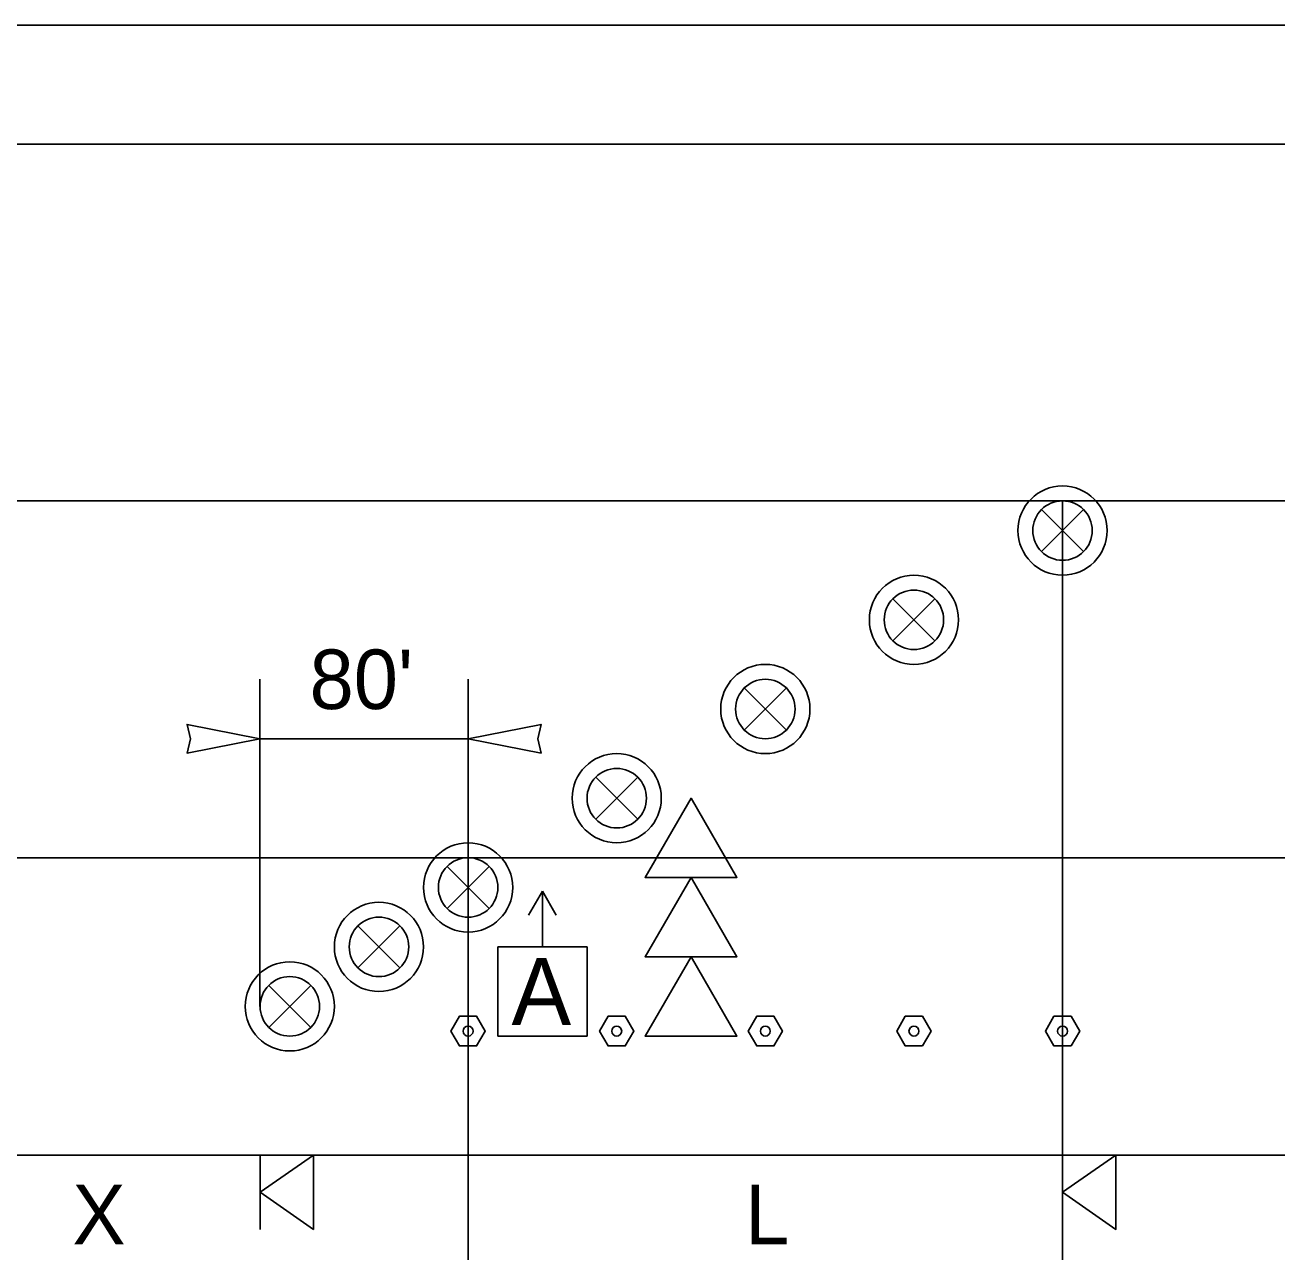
# Model space of a CAD drawing. Extents: x 99958 to 100136, y 99935 to 100013.
# Drawn here: x 100025.894 to 100027.579, y 99975.105 to 99976.756 of the extents above; entities that cross this region are included whole.
import ezdxf

# ---------------------------------------------------------------- set-up
doc = ezdxf.new("R2010")
doc.units = 0
for name, color, linetype in [('RD_ED_ShoulderPavedEdge', 7, 'Continuous'), ('RD_MK_LineEdgeWhite', 7, 'Continuous'), ('RD_MK_LineEdgeYellow', 7, 'Continuous'), ('RD_MK_LineLane', 7, 'Continuous'), ('TR_WZ_PortableSignMountBlk-Wht', 7, 'Continuous'), ('TR_WZ_SequentialArrowSign', 7, 'Continuous'), ('TR_WZ_TrafficSafetyDrum', 7, 'Continuous'), ('TR_WZ_TubularMarker', 7, 'Continuous'), ('TR_WZ_WorkZoneDetails', 7, 'Continuous'), ('TR_WZ_WorkZoneTextCurrent', 7, 'Continuous')]:
    doc.layers.add(name, color=color, linetype=linetype)

msp = doc.modelspace()

# ---------------------------------------------------------------- linework, layer by layer
at = {"layer": 'RD_ED_ShoulderPavedEdge'}
for p, q in [((100021.7753, 99976.7557), (100035.62, 99976.7557)), ((100021.7753, 99975.2357), (100035.62, 99975.2357))]:
    msp.add_line(p, q, dxfattribs=at)
at = {"layer": 'RD_MK_LineEdgeWhite'}
msp.add_line((100021.7753, 99975.6357), (100035.62, 99975.6357), dxfattribs=at)
at = {"layer": 'RD_MK_LineEdgeYellow'}
msp.add_line((100021.7753, 99976.5957), (100035.62, 99976.5957), dxfattribs=at)
at = {"layer": 'RD_MK_LineLane'}
msp.add_lwpolyline([(100035.62, 99976.1157), (100021.7753, 99976.1157)], dxfattribs=at)
at = {"layer": 'TR_WZ_PortableSignMountBlk-Wht'}
for p, q in [((100026.2103, 99975.1357), (100026.2103, 99975.2357)), ((100027.2902, 99975.1357), (100027.2902, 99975.2357))]:
    msp.add_line(p, q, dxfattribs=at)
for points in [[(100026.2103, 99975.1856), (100026.2821, 99975.2357), (100026.2821, 99975.1357)], [(100027.2902, 99975.1856), (100027.3621, 99975.2357), (100027.3621, 99975.1357)]]:
    msp.add_lwpolyline(points, close=True, dxfattribs=at)
at = {"layer": 'TR_WZ_SequentialArrowSign'}
for points in [[(100026.7903, 99975.7157), (100026.7285, 99975.6091), (100026.7903, 99975.6091), (100026.852, 99975.6091), (100026.7903, 99975.7157)], [(100026.852, 99975.6091), (100026.7903, 99975.6091), (100026.7285, 99975.6091), (100026.7903, 99975.7157), (100026.852, 99975.6091)], [(100026.7903, 99975.6091), (100026.7285, 99975.5024), (100026.7903, 99975.5024), (100026.852, 99975.5024), (100026.7903, 99975.6091)], [(100026.852, 99975.5024), (100026.7903, 99975.5024), (100026.7285, 99975.5024), (100026.7903, 99975.6091), (100026.852, 99975.5024)], [(100026.7903, 99975.5024), (100026.7285, 99975.3957), (100026.852, 99975.3957), (100026.7903, 99975.5024)], [(100026.852, 99975.3957), (100026.7285, 99975.3957), (100026.7903, 99975.5024), (100026.852, 99975.3957)]]:
    msp.add_lwpolyline(points, dxfattribs=at)
at = {"layer": 'TR_WZ_TrafficSafetyDrum'}
for p, q in [((100027.262, 99976.104), (100027.3186, 99976.0474)), ((100027.3186, 99976.104), (100027.262, 99976.0474)), ((100027.062, 99975.984), (100027.1186, 99975.9274)), ((100027.1186, 99975.984), (100027.062, 99975.9274)), ((100026.862, 99975.864), (100026.9186, 99975.8074)), ((100026.9186, 99975.864), (100026.862, 99975.8074)), ((100026.662, 99975.744), (100026.7186, 99975.6874)), ((100026.7186, 99975.744), (100026.662, 99975.6874)), ((100026.462, 99975.624), (100026.5186, 99975.5674)), ((100026.5186, 99975.624), (100026.462, 99975.5674)), ((100026.342, 99975.544), (100026.3986, 99975.4874)), ((100026.3986, 99975.544), (100026.342, 99975.4874)), ((100026.222, 99975.464), (100026.2786, 99975.4074)), ((100026.2786, 99975.464), (100026.222, 99975.4074))]:
    msp.add_line(p, q, dxfattribs=at)
for centre, radius in [((100027.2903, 99976.0757), 0.06), ((100027.2903, 99976.0757), 0.06), ((100027.2903, 99976.0757), 0.04), ((100027.0903, 99975.9557), 0.06), ((100027.0903, 99975.9557), 0.06), ((100027.0903, 99975.9557), 0.04), ((100026.8903, 99975.8357), 0.06), ((100026.8903, 99975.8357), 0.06), ((100026.8903, 99975.8357), 0.04), ((100026.6903, 99975.7157), 0.06), ((100026.6903, 99975.7157), 0.06), ((100026.6903, 99975.7157), 0.04), ((100026.4903, 99975.5957), 0.06), ((100026.4903, 99975.5957), 0.06), ((100026.4903, 99975.5957), 0.04), ((100026.3703, 99975.5157), 0.06), ((100026.3703, 99975.5157), 0.06), ((100026.3703, 99975.5157), 0.04), ((100026.2503, 99975.4357), 0.06), ((100026.2503, 99975.4357), 0.06), ((100026.2503, 99975.4357), 0.04)]:
    msp.add_circle(centre, radius, dxfattribs=at)
at = {"layer": 'TR_WZ_TubularMarker'}
for points in [[(100026.4672, 99975.4024), (100026.4787, 99975.4224), (100026.5018, 99975.4224), (100026.5134, 99975.4024), (100026.5018, 99975.3824), (100026.4787, 99975.3824)], [(100026.6672, 99975.4024), (100026.6787, 99975.4224), (100026.7018, 99975.4224), (100026.7134, 99975.4024), (100026.7018, 99975.3824), (100026.6787, 99975.3824)], [(100026.8672, 99975.4024), (100026.8787, 99975.4224), (100026.9018, 99975.4224), (100026.9134, 99975.4024), (100026.9018, 99975.3824), (100026.8787, 99975.3824)], [(100027.0672, 99975.4024), (100027.0787, 99975.4224), (100027.1018, 99975.4224), (100027.1134, 99975.4024), (100027.1018, 99975.3824), (100027.0787, 99975.3824)], [(100027.2672, 99975.4024), (100027.2787, 99975.4224), (100027.3018, 99975.4224), (100027.3134, 99975.4024), (100027.3018, 99975.3824), (100027.2787, 99975.3824)]]:
    msp.add_lwpolyline(points, close=True, dxfattribs=at)
for points in [[(100026.4787, 99975.3824), (100026.5018, 99975.3824), (100026.5134, 99975.4024), (100026.5018, 99975.4224), (100026.4787, 99975.4224), (100026.4672, 99975.4024), (100026.4787, 99975.3824)], [(100026.6787, 99975.3824), (100026.7018, 99975.3824), (100026.7134, 99975.4024), (100026.7018, 99975.4224), (100026.6787, 99975.4224), (100026.6672, 99975.4024), (100026.6787, 99975.3824)], [(100026.8787, 99975.3824), (100026.9018, 99975.3824), (100026.9134, 99975.4024), (100026.9018, 99975.4224), (100026.8787, 99975.4224), (100026.8672, 99975.4024), (100026.8787, 99975.3824)], [(100027.0787, 99975.3824), (100027.1018, 99975.3824), (100027.1134, 99975.4024), (100027.1018, 99975.4224), (100027.0787, 99975.4224), (100027.0672, 99975.4024), (100027.0787, 99975.3824)], [(100027.2787, 99975.3824), (100027.3018, 99975.3824), (100027.3134, 99975.4024), (100027.3018, 99975.4224), (100027.2787, 99975.4224), (100027.2672, 99975.4024), (100027.2787, 99975.3824)]]:
    msp.add_lwpolyline(points, dxfattribs=at)
for centre in [(100026.4903, 99975.4024), (100026.6903, 99975.4024), (100026.8903, 99975.4024), (100027.0903, 99975.4024), (100027.2903, 99975.4024)]:
    msp.add_circle(centre, 0.00667, dxfattribs=at)
at = {"layer": 'TR_WZ_WorkZoneDetails'}
for p, q in [((100027.2902, 99976.1157), (100027.2902, 99974.598)), ((100026.2102, 99975.8757), (100026.2102, 99975.4357)), ((100026.4902, 99975.8757), (100026.4902, 99974.9957)), ((100026.4902, 99975.7957), (100026.2102, 99975.7957)), ((100026.5903, 99975.5907), (100026.5715, 99975.5583)), ((100026.5903, 99975.5157), (100026.5903, 99975.5907)), ((100026.5903, 99975.5907), (100026.609, 99975.5583))]:
    msp.add_line(p, q, dxfattribs=at)
for points in [[(100026.2102, 99975.7957), (100026.112, 99975.7765), (100026.1165, 99975.7957), (100026.112, 99975.815)], [(100026.4902, 99975.7957), (100026.5885, 99975.7765), (100026.584, 99975.7957), (100026.5885, 99975.815)], [(100026.5303, 99975.5157), (100026.6503, 99975.5157), (100026.6503, 99975.3957), (100026.5303, 99975.3957)]]:
    msp.add_lwpolyline(points, close=True, dxfattribs=at)
msp.add_lwpolyline([(100026.5303, 99975.5157), (100026.5303, 99975.3957), (100026.6503, 99975.3957), (100026.6503, 99975.5157), (100026.5903, 99975.5157), (100026.5303, 99975.5157)], dxfattribs=at)

# ---------------------------------------------------------------- texts
msp.add_text('A', height=0.09, dxfattribs=at).set_placement((100026.5487, 99975.4107))
at = {"layer": 'TR_WZ_WorkZoneTextCurrent'}
msp.add_text("80'", height=0.08, dxfattribs=at).set_placement((100026.2769, 99975.8357))
for s, p in [('X', (100025.9578, 99975.1157)), ('L', (100026.8631, 99975.1157))]:
    msp.add_text(s, height=0.08, rotation=360, dxfattribs=at).set_placement(p)

doc.saveas('drawing.dxf')
